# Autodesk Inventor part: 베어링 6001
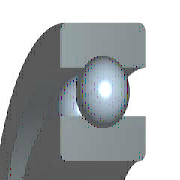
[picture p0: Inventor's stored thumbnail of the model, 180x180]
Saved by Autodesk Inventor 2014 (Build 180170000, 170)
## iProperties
Created: 2012-02
Part Number: 베어링 6001
Material: 강철, 연강
Description: 깊은 그루브 볼 베어링
Document SubType Name: Modeling
Standard: KS B 2023
Designer: mduedu
Standards Organization: KS
Language: ko-KR
Size Designation: 6001 - 12 x 28 x 8
Categories: <MemberInstance><Categories><Category DisplayName="샤프트 부품" InternalName="7f7aeb1f-a693-4053-b835-cee3144e0d98" Mnemonic="SHFT"><Category DisplayName="베어링" Inter
Density: 7.86 g/cm^3
Mass: 21.4855 g
Surface Area: 31.1809 cm^2
Volume: 2.73352 cm^3
Appearance: Yellow
IsCustomPart: 1
Author: mduedu
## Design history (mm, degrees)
sketch "스케치" dims "d0" = 4.16 (= -0.26 x WD + 0.26 x BD)
  geometry: L1 (1.92, 10)-(6.08, 10); L2 (4, 10)-(4, 7.92); L3 (4, 10)-(4, 12.08); L4 (2.454, 8.608)-(0, 8.608); L5 (0, 6)-(8, 6); L6 (2.454, 11.392)-(0, 11.392); L7 (0, 14)-(8, 14); L8 (8, 6)-(8, 8.608); L9 (5.546, 8.608)-(8, 8.608); L10 (5.546, 11.392)-(8, 11.392); L11 (8, 14)-(8, 11.392); L12 (-1.4, 0)-(8.4, 0) reference; L13 (0, -0.3)-(0, 5.3) reference
  constraints: 22 end point, 4 point on line, 2 collinear, 2 perpendicular, 2 symmetric about line, 1 midpoint, 1 parallel, 14 other
  dimensions: "d9" = 12 diameter of L5 L12 (= WD); "d11" = 28 diameter of L7 L12 (= BD); "d12" = 8 distance between parallel lines of L8 L13 (= KB); "d13" = 17.216 diameter of L9 L12 (= 0.326 x BD + 0.674 x WD)
revolve "본체" stored, may be unused: angle "d6" = 90 deg
revolve "볼" stored, may be unused: angle "d7" = 90 deg
pattern_circular "IDS_ARRAYBALL[SIMPL:T]" dims angle "d3" = 360 deg
body "Solid1"
fillet "모깎기1" dims "d1" = 0.3 (= KRS)
other parameters: "WD" = 12 [user parameter; used in 5 equation terms], "BD" = 28 [user parameter; used in 5 equation terms], "KB" = 8 [user parameter; used in 1 equation term], "KRS" = 0.3 [user parameter; used in 1 equation term], "d4" = 0, "d5" = 0, "d8" = 0, "d14" = 0, "d15" = 0, "BBA" = 0 [user parameter], "BC0" = 2360000 [user parameter], "BC" = 5070000 [user parameter], "BR" = 14 (= 0.5 x BD) [user parameter], "WR" = 6 (= 0.5 x WD) [user parameter]
